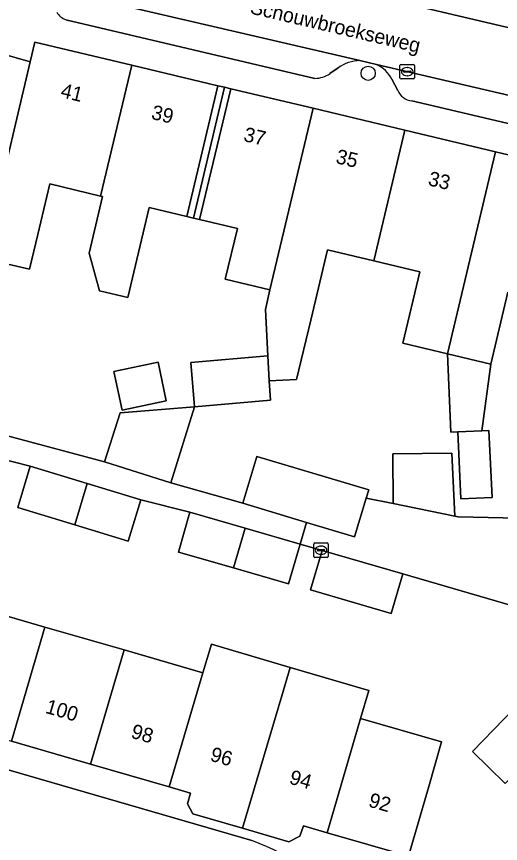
# Model space of a CAD drawing. Extents: x 159716 to 160783, y 383290 to 384031.
# Drawn here: x 160051.8 to 160085.2, y 383432.6 to 383489.6 of the extents above; entities that cross this region are included whole.
import ezdxf

# ---------------------------------------------------------------- set-up
doc = ezdxf.new("R2010")
doc.units = 0
for name, color, linetype in [('IMGEO_Boom', 7, 'Continuous'), ('IMGEO_Erf', 7, 'Continuous'), ('IMGEO_Kolk', 7, 'Continuous'), ('IMGEO_Openbare_ruimte_label', 7, 'Continuous'), ('IMGEO_Pand', 7, 'Continuous'), ('IMGEO_Pand_nummerreeks', 7, 'Continuous'), ('IMGEO_Pand_overbouw', 7, 'Continuous'), ('IMGEO_Parkeervlak_open', 7, 'Continuous'), ('IMGEO_Rijbaan_lokaal_open', 7, 'Continuous'), ('IMGEO_Voetpad_open', 7, 'Continuous')]:
    doc.layers.add(name, color=color, linetype=linetype)

msp = doc.modelspace()

# ---------------------------------------------------------------- linework, layer by layer
at = {"layer": 'IMGEO_Boom'}
msp.add_circle((160076.039, 383485.657), 0.489, dxfattribs=at)
at = {"layer": 'IMGEO_Erf'}
for points in [[(160050.108, 383475.315), (160051.921, 383482.942), (160052.755, 383486.447), (160018.953, 383496.159)], [(160045.936, 383462.099), (160057.878, 383458.909), (160058.95, 383462.289), (160064.076, 383462.698), (160063.815, 383465.739), (160069.136, 383466.195), (160068.96, 383469.393), (160069.269, 383470.758), (160066.2, 383471.487), (160067.028, 383474.966), (160064.426, 383475.585), (160063.996, 383475.687), (160063.548, 383475.793), (160060.946, 383476.412), (160059.472, 383470.215), (160057.526, 383470.678), (160056.808, 383473.283), (160057.734, 383477.174), (160057.602, 383477.205), (160054.101, 383478.038), (160053.275, 383474.562), (160052.705, 383472.162), (160050.916, 383472.587)], [(160085.673, 383470.591), (160084.494, 383465.632), (160083.873, 383461.046), (160084.356, 383461.069), (160084.575, 383456.457), (160082.436, 383456.356), (160082.217, 383460.967), (160081.729, 383460.944), (160081.51, 383466.341), (160078.436, 383467.072), (160079.605, 383471.988), (160076.43, 383472.743), (160073.234, 383473.503), (160072.08, 383468.651), (160071.113, 383464.585), (160069.23, 383464.484), (160069.304, 383463.146), (160064.076, 383462.698), (160062.435, 383457.464), (160067.415, 383456.051), (160068.381, 383459.279), (160076.076, 383456.977), (160075.908, 383456.416), (160077.765, 383456.037), (160077.735, 383459.468), (160081.797, 383459.503), (160082.003, 383455.173), (160082.244, 383455.124), (160095.725, 383454.815)], [(160094.656, 383446.476), (160078.421, 383451.191), (160077.635, 383448.476), (160072.074, 383450.085), (160072.861, 383452.801), (160071.353, 383453.243), (160070.559, 383450.501), (160066.763, 383451.6), (160062.966, 383452.699), (160063.76, 383455.441), (160060.37, 383456.296), (160059.507, 383453.452), (160055.837, 383454.566), (160051.9, 383455.762), (160052.763, 383458.605), (160049.499, 383459.443)], [(160005.837, 383450.845), (160068.032, 383432.838)], [(160048.327, 383449.109), (160053.77, 383447.533), (160059.222, 383445.954), (160064.655, 383444.381), (160065.24, 383446.362), (160070.659, 383444.76), (160076.082, 383443.158), (160075.521, 383441.235), (160081.1, 383439.62), (160080.212, 383436.553), (160078.822, 383431.75), (160073.225, 383433.37), (160071.587, 383433.844), (160071.336, 383433.136), (160070.565, 383432.757), (160067.388, 383433.684), (160063.961, 383434.68), (160063.599, 383435.37), (160063.809, 383436.097), (160062.333, 383436.524), (160056.901, 383438.096), (160051.46, 383439.672)], [(160085.49, 383436.765), (160083.222, 383438.958), (160087.588, 383443.472)]]:
    msp.add_lwpolyline(points, dxfattribs=at)
for points in [[(160063.996, 383475.687), (160066.143, 383484.697), (160065.695, 383484.803), (160063.548, 383475.793)], [(160064.426, 383475.585), (160066.573, 383484.595), (160066.143, 383484.697), (160063.996, 383475.687)], [(160061.564, 383465.765), (160062.129, 383463.11), (160059.085, 383462.462), (160058.52, 383465.118)]]:
    msp.add_lwpolyline(points, close=True, dxfattribs=at)
msp.add_arc((160054.691, 383399.299), 36.095, 54.5346, 68.3089, dxfattribs=at)
at = {"layer": 'IMGEO_Kolk'}
for p, q in [((160078.233, 383485.343), (160078.233, 383486.195)), ((160078.308, 383486.269), (160079.16, 383486.269)), ((160078.535, 383485.812), (160078.933, 383485.812)), ((160078.721, 383486.049), (160078.746, 383486.049)), ((160079.234, 383486.195), (160079.234, 383485.343)), ((160079.16, 383485.269), (160078.308, 383485.269)), ((160078.492, 383485.763), (160078.492, 383485.775)), ((160078.93, 383485.726), (160078.532, 383485.726)), ((160078.744, 383485.489), (160078.719, 383485.489)), ((160078.976, 383485.775), (160078.976, 383485.763)), ((160072.294, 383452.398), (160072.294, 383453.25)), ((160072.369, 383453.324), (160073.221, 383453.324)), ((160072.553, 383452.818), (160072.553, 383452.83)), ((160072.596, 383452.867), (160072.994, 383452.867)), ((160072.782, 383453.104), (160072.807, 383453.104)), ((160073.037, 383452.83), (160073.037, 383452.818)), ((160073.295, 383453.25), (160073.295, 383452.398)), ((160073.221, 383452.324), (160072.369, 383452.324)), ((160072.991, 383452.781), (160072.593, 383452.781)), ((160072.805, 383452.544), (160072.78, 383452.544))]:
    msp.add_line(p, q, dxfattribs=at)
for points in [[(160078.233, 383485.343), (160078.233, 383486.195)], [(160078.308, 383486.269), (160079.16, 383486.269)], [(160079.234, 383486.195), (160079.234, 383485.343)], [(160079.16, 383485.269), (160078.308, 383485.269)], [(160072.294, 383452.398), (160072.294, 383453.25)], [(160072.369, 383453.324), (160073.221, 383453.324)], [(160073.295, 383453.25), (160073.295, 383452.398)], [(160073.221, 383452.324), (160072.369, 383452.324)]]:
    msp.add_lwpolyline(points, dxfattribs=at)
for centre, radius, start, end in [((160078.31, 383486.193), 0.0765, 91.552, 178.448), ((160078.31, 383486.193), 0.0765, 91.552, 178.448), ((160078.532, 383485.772), 0.0403, 85.8775, 175.7526), ((160078.937, 383485.774), 0.0386, 1.7309, 96.639), ((160079.158, 383486.193), 0.0765, 1.552, 88.448), ((160079.158, 383486.193), 0.0765, 1.552, 88.448), ((160078.31, 383485.345), 0.0765, 181.552, 268.448), ((160078.31, 383485.345), 0.0765, 181.552, 268.448), ((160078.529, 383485.762), 0.0366, 178.938, 274.7102), ((160078.933, 383485.769), 0.043, 264.8664, 352.4533), ((160079.158, 383485.345), 0.0765, 271.552, 358.448), ((160079.158, 383485.345), 0.0765, 271.552, 358.448), ((160072.371, 383453.248), 0.0765, 91.552, 178.448), ((160072.371, 383453.248), 0.0765, 91.552, 178.448), ((160072.593, 383452.827), 0.0403, 85.8775, 175.7526), ((160072.59, 383452.817), 0.0366, 178.938, 274.7102), ((160072.994, 383452.824), 0.043, 264.8664, 352.4533), ((160072.998, 383452.829), 0.0386, 1.7309, 96.639), ((160073.219, 383453.248), 0.0765, 1.552, 88.448), ((160073.219, 383453.248), 0.0765, 1.552, 88.448), ((160072.371, 383452.4), 0.0765, 181.552, 268.448), ((160072.371, 383452.4), 0.0765, 181.552, 268.448), ((160073.219, 383452.4), 0.0765, 271.552, 358.448), ((160073.219, 383452.4), 0.0765, 271.552, 358.448)]:
    msp.add_arc(centre, radius, start, end, dxfattribs=at)
for centre, major_axis, ratio, start_param, end_param in [((160078.72, 383485.769), (-0.387, 0.002), 0.722429, 4.712389, 7.853982), ((160078.745, 383485.769), (-0.39, 0.002), 0.717154, 1.570796, 4.712389), ((160072.781, 383452.824), (-0.387, 0.002), 0.722429, 4.712389, 7.853982), ((160072.806, 383452.824), (-0.39, 0.002), 0.717154, 1.570796, 4.712389)]:
    msp.add_ellipse(centre, major_axis=major_axis, ratio=ratio, start_param=start_param, end_param=end_param, dxfattribs=at)
at = {"layer": 'IMGEO_Pand'}
for points in [[(160059.75, 383486.218), (160053.078, 383487.806), (160052.755, 383486.447), (160051.921, 383482.942), (160050.108, 383475.315), (160050.916, 383472.587), (160052.705, 383472.162), (160053.275, 383474.562), (160054.101, 383478.038), (160057.602, 383477.205)], [(160057.602, 383477.205), (160057.734, 383477.174), (160056.808, 383473.283), (160057.526, 383470.678), (160059.472, 383470.215), (160060.946, 383476.412), (160063.548, 383475.793), (160065.695, 383484.803), (160059.75, 383486.218)], [(160069.269, 383470.758), (160072.241, 383483.245), (160066.573, 383484.595), (160064.426, 383475.585), (160067.028, 383474.966), (160066.2, 383471.487)], [(160078.573, 383481.738), (160072.241, 383483.245), (160069.269, 383470.758), (160068.96, 383469.393), (160069.136, 383466.195), (160069.23, 383464.484), (160071.113, 383464.585), (160072.08, 383468.651), (160073.234, 383473.503), (160076.43, 383472.743)], [(160078.573, 383481.738), (160076.43, 383472.743), (160079.605, 383471.988), (160078.436, 383467.072), (160081.51, 383466.341), (160084.822, 383480.251)], [(160091.522, 383478.657), (160090.156, 383478.982), (160084.822, 383480.251), (160081.51, 383466.341), (160084.494, 383465.632), (160085.673, 383470.591), (160089.349, 383469.717)], [(160069.23, 383464.484), (160069.136, 383466.195), (160063.815, 383465.739), (160064.076, 383462.698), (160069.304, 383463.146)], [(160084.494, 383465.632), (160081.51, 383466.341), (160081.729, 383460.944), (160082.217, 383460.967), (160083.873, 383461.046)], [(160058.52, 383465.118), (160059.085, 383462.462), (160062.129, 383463.11), (160061.564, 383465.765)], [(160064.076, 383462.698), (160058.95, 383462.289), (160057.878, 383458.909), (160062.435, 383457.464)], [(160083.873, 383461.046), (160082.217, 383460.967), (160082.436, 383456.356), (160084.575, 383456.457), (160084.356, 383461.069)], [(160075.908, 383456.416), (160076.076, 383456.977), (160068.381, 383459.279), (160067.415, 383456.051), (160071.803, 383454.738), (160075.11, 383453.749)], [(160081.797, 383459.503), (160077.735, 383459.468), (160077.765, 383456.037), (160082.003, 383455.173)], [(160055.837, 383454.566), (160056.675, 383457.417), (160052.763, 383458.605), (160051.9, 383455.762)], [(160055.837, 383454.566), (160059.507, 383453.452), (160060.37, 383456.296), (160056.675, 383457.417)], [(160066.763, 383451.6), (160067.556, 383454.342), (160063.76, 383455.441), (160062.966, 383452.699)], [(160066.763, 383451.6), (160070.559, 383450.501), (160071.353, 383453.243), (160067.556, 383454.342)], [(160078.421, 383451.191), (160072.861, 383452.801), (160072.074, 383450.085), (160077.635, 383448.476)], [(160048.327, 383449.109), (160046.019, 383441.247), (160051.46, 383439.672), (160053.77, 383447.533)], [(160059.222, 383445.954), (160053.77, 383447.533), (160051.46, 383439.672), (160056.901, 383438.096)], [(160064.655, 383444.381), (160062.333, 383436.524), (160063.809, 383436.097), (160063.599, 383435.37), (160063.961, 383434.68), (160067.388, 383433.684), (160070.097, 383442.806), (160070.659, 383444.76), (160065.24, 383446.362)], [(160059.222, 383445.954), (160056.901, 383438.096), (160062.333, 383436.524), (160064.655, 383444.381)], [(160075.521, 383441.235), (160076.082, 383443.158), (160070.659, 383444.76), (160070.097, 383442.806), (160067.388, 383433.684), (160070.565, 383432.757), (160071.336, 383433.136), (160071.587, 383433.844), (160073.225, 383433.37)], [(160089.651, 383441.477), (160087.588, 383443.472), (160083.222, 383438.958), (160085.49, 383436.765), (160089.86, 383441.275)], [(160075.521, 383441.235), (160073.225, 383433.37), (160078.822, 383431.75), (160080.212, 383436.553), (160081.1, 383439.62)]]:
    msp.add_lwpolyline(points, close=True, dxfattribs=at)
at = {"layer": 'IMGEO_Pand_overbouw'}
for points in [[(160065.695, 383484.803), (160063.548, 383475.793), (160063.996, 383475.687), (160066.143, 383484.697)], [(160066.143, 383484.697), (160063.996, 383475.687), (160064.426, 383475.585), (160066.573, 383484.595)]]:
    msp.add_lwpolyline(points, close=True, dxfattribs=at)
at = {"layer": 'IMGEO_Parkeervlak_open'}
for points in [[(160030.39, 383501.718), (160037.998, 383500), (160115.615, 383481.783), (160115.214, 383481.919), (160114.99, 383482.038), (160114.733, 383482.223), (160114.438, 383482.525), (160114.058, 383483.274)], [(160075.473, 383486.534), (160053.073, 383491.741)], [(160055.21, 383489.348), (160072.357, 383485.308)], [(160073.411, 383485.637), (160073.983, 383486.043)], [(160114.655, 383477.395), (160076.614, 383486.267)], [(160077.676, 383485.252), (160078.081, 383484.477)], [(160079.045, 383483.765), (160090.672, 383481.032), (160111.471, 383476.142)]]:
    msp.add_lwpolyline(points, dxfattribs=at)
for centre, radius, start, end in [((160055.54, 383490.355), 1.059, 206.9835, 251.8447), ((160075.545, 383483.808), 2.727, 91.5194, 124.9578), ((160075.573, 383484.115), 2.391, 28.4025, 64.1901), ((160072.352, 383487.178), 1.87, 270.1671, 304.5038), ((160079.171, 383484.945), 1.187, 203.2211, 263.8806)]:
    msp.add_arc(centre, radius, start, end, dxfattribs=at)
at = {"layer": 'IMGEO_Rijbaan_lokaal_open'}
msp.add_lwpolyline([(160037.998, 383500), (160030.39, 383501.718), (160026.229, 383503.016), (160025.764, 383503.184), (160025.553, 383503.261), (160025.287, 383503.349), (160023.952, 383498.899), (160026.851, 383497.979), (160029.484, 383497.298), (160049.062, 383492.672), (160049.223, 383492.632), (160052.896, 383491.782), (160053.073, 383491.741), (160075.473, 383486.534), (160076.614, 383486.267), (160114.655, 383477.395), (160114.912, 383477.335), (160115.92, 383481.713), (160115.615, 383481.783)], close=True, dxfattribs=at)
msp.add_lwpolyline([(160112.006, 383428.209), (160107.952, 383436.294), (160104.043, 383444.455), (160101.533, 383449.003), (160101.672, 383449.081), (160100.39, 383451.618), (160095.725, 383454.815), (160082.244, 383455.124), (160082.003, 383455.173), (160077.765, 383456.037), (160075.908, 383456.416), (160075.11, 383453.749), (160071.803, 383454.738), (160071.353, 383453.243), (160072.861, 383452.801), (160078.421, 383451.191), (160094.656, 383446.476), (160094.778, 383446.407), (160097.112, 383441.527), (160099.933, 383435.581), (160101.55, 383432.432)], dxfattribs=at)
at = {"layer": 'IMGEO_Voetpad_open'}
for points in [[(160068.032, 383432.838), (160005.837, 383450.845), (160012.364, 383473.397), (160012.776, 383474.819), (160018.953, 383496.159), (160016.186, 383497.035), (160016.093, 383496.718)], [(160018.953, 383496.159), (160052.755, 383486.447), (160053.078, 383487.806), (160059.75, 383486.218), (160065.695, 383484.803), (160066.143, 383484.697), (160066.573, 383484.595), (160072.241, 383483.245), (160078.573, 383481.738), (160084.822, 383480.251), (160090.156, 383478.982), (160091.522, 383478.657), (160097.775, 383477.168), (160098.34, 383477.034), (160103.922, 383475.636), (160108.363, 383474.524), (160115.993, 383472.788)], [(160072.357, 383485.308), (160055.21, 383489.348)], [(160076.614, 383486.267), (160075.473, 383486.534)], [(160073.983, 383486.043), (160073.411, 383485.637)], [(160078.081, 383484.477), (160077.676, 383485.252)], [(160111.471, 383476.142), (160090.672, 383481.032), (160079.045, 383483.765)]]:
    msp.add_lwpolyline(points, dxfattribs=at)
msp.add_lwpolyline([(160045.936, 383462.099), (160041.115, 383463.427), (160040.804, 383463.513), (160040.406, 383462.203), (160041.892, 383461.752), (160045.792, 383460.568), (160049.499, 383459.443), (160052.763, 383458.605), (160056.675, 383457.417), (160060.37, 383456.296), (160063.76, 383455.441), (160067.556, 383454.342), (160071.353, 383453.243), (160071.803, 383454.738), (160067.415, 383456.051), (160062.435, 383457.464), (160057.878, 383458.909)], close=True, dxfattribs=at)
for centre, radius, start, end in [((160055.54, 383490.355), 1.059, 206.9835, 251.8447), ((160075.545, 383483.808), 2.727, 91.5194, 124.9578), ((160075.573, 383484.115), 2.391, 28.4025, 64.1901), ((160072.352, 383487.178), 1.87, 270.1671, 304.5038), ((160079.171, 383484.945), 1.187, 203.2211, 263.8806), ((160054.691, 383399.299), 36.095, 54.5346, 68.3089)]:
    msp.add_arc(centre, radius, start, end, dxfattribs=at)

# ---------------------------------------------------------------- texts
at = {"layer": 'IMGEO_Openbare_ruimte_label'}
msp.add_text('Schouwbroekseweg', height=1, rotation=346.8251, dxfattribs=at).set_placement((160067.851, 383489.783))
at = {"layer": 'IMGEO_Pand_nummerreeks'}
for s, rotation, p in [('41', 346.5412, (160054.799, 383484.022)), ('39', 346.5391, (160061.044, 383482.526)), ('37', 346.5391, (160067.4, 383481.005)), ('35', 346.5412, (160073.755, 383479.484)), ('33', 346.5391, (160080.111, 383477.962)), ('100', 343.8536, (160053.742, 383441.635)), ('98', 343.8536, (160059.639, 383439.927)), ('96', 343.8536, (160065.091, 383438.348)), ('94', 343.8536, (160070.546, 383436.769)), ('92', 343.8536, (160075.999, 383435.19))]:
    msp.add_text(s, height=1, rotation=rotation, dxfattribs=at).set_placement(p)

doc.saveas('drawing.dxf')
